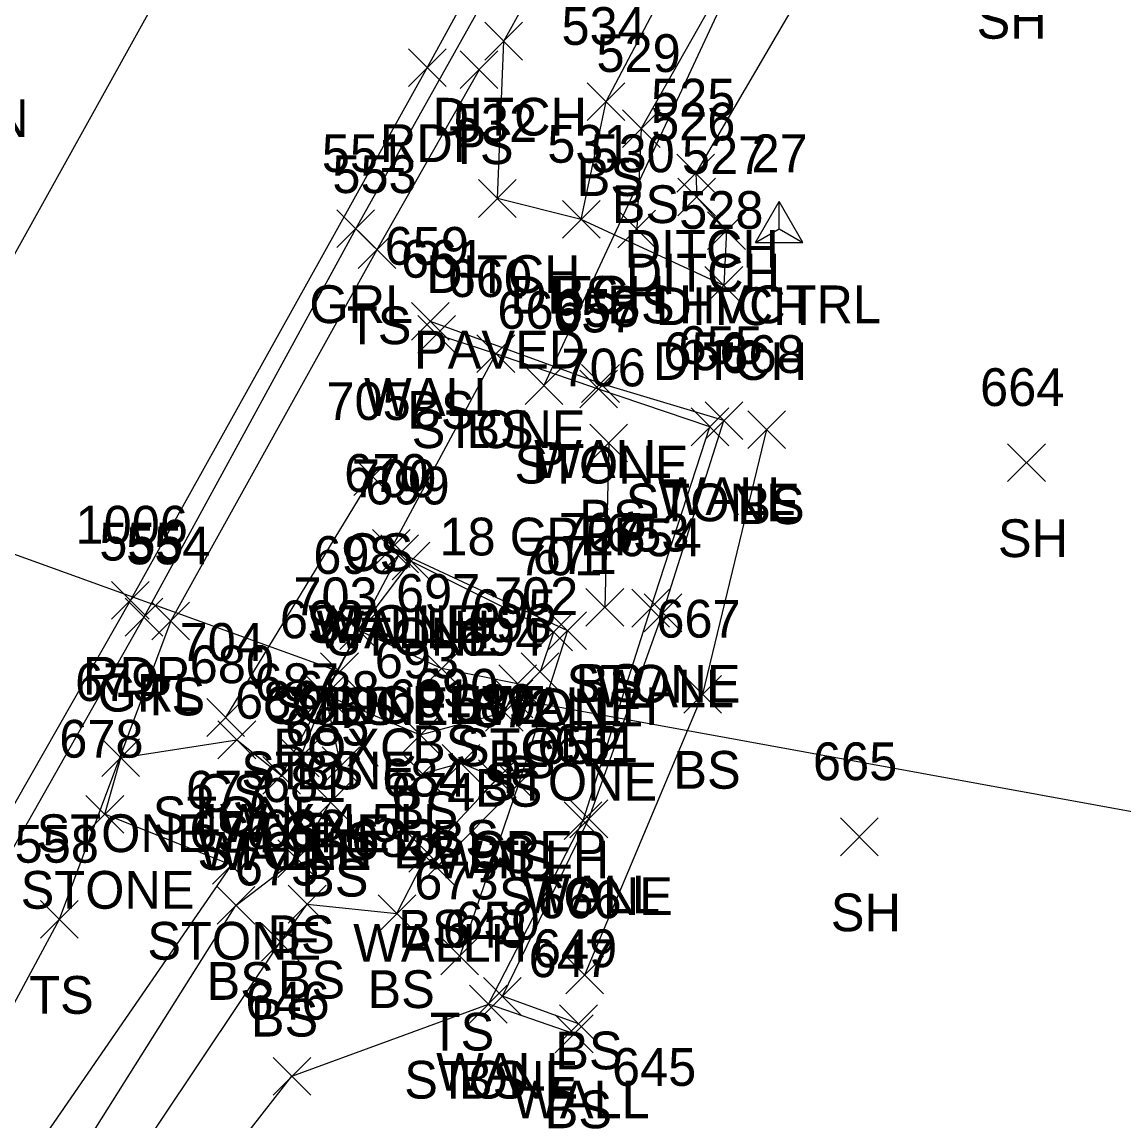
# Model space of a CAD drawing. Extents: x 1639430 to 1640195, y 612006 to 612917.
# Drawn here: x 1639849.6 to 1639907.9, y 612574.5 to 612632.7 of the extents above; entities that cross this region are included whole.
import ezdxf

# ---------------------------------------------------------------- set-up
doc = ezdxf.new("R2010")
doc.units = 0
for name, color, linetype in [('C_A', 7, 'Continuous'), ('C_C', 7, 'Continuous'), ('C_I', 7, 'Continuous'), ('CPSM', 7, 'Continuous'), ('D_A', 7, 'Continuous'), ('D_C', 7, 'Continuous'), ('D_I', 7, 'Continuous'), ('D_TIC', 7, 'Continuous'), ('DCP', 7, 'Continuous'), ('DD', 7, 'Continuous'), ('DDEFAULT', 7, 'Continuous'), ('DHW', 7, 'Continuous'), ('L_A', 7, 'Continuous'), ('L_I', 7, 'Continuous'), ('L_TIC', 7, 'Continuous'), ('LASF', 7, 'Continuous'), ('LELB', 7, 'Continuous'), ('LW', 7, 'Continuous'), ('P_A', 7, 'Continuous'), ('P_I', 7, 'Continuous'), ('P_TIC', 7, 'Continuous'), ('PET', 7, 'Continuous'), ('PRC', 7, 'Continuous'), ('R_A', 7, 'Continuous'), ('R_I', 7, 'Continuous'), ('R_TIC', 7, 'Continuous'), ('RGR', 7, 'Continuous')]:
    doc.layers.add(name, color=color, linetype=linetype)

msp = doc.modelspace()

# ---------------------------------------------------------------- linework, layer by layer
at = {"layer": 'CPSM'}
for p, q in [((1639888.428, 612621.012), (1639889.678, 612623.177)), ((1639890.928, 612621.012), (1639889.678, 612623.177)), ((1639889.678, 612621.733), (1639889.678, 612623.177)), ((1639888.428, 612621.012), (1639889.678, 612621.733)), ((1639889.678, 612621.733), (1639889.678, 612621.733)), ((1639889.678, 612621.733), (1639890.928, 612621.012)), ((1639888.428, 612621.012), (1639890.928, 612621.012))]:
    msp.add_line(p, q, dxfattribs=at)
at = {"layer": 'D_TIC'}
for points in [[(1639874.09, 612630.669), (1639876.09, 612632.669)], [(1639876.09, 612630.669), (1639874.09, 612632.669)], [(1639884.255, 612623.678), (1639886.255, 612625.678)], [(1639886.255, 612623.678), (1639884.255, 612625.678)], [(1639884.313, 612622.413), (1639886.313, 612624.413)], [(1639886.313, 612622.413), (1639884.313, 612624.413)], [(1639873.754, 612622.337), (1639875.754, 612624.337)], [(1639875.754, 612622.337), (1639873.754, 612624.337)], [(1639878.193, 612621.233), (1639880.193, 612623.233)], [(1639880.193, 612621.233), (1639878.193, 612623.233)], [(1639885.889, 612620.636), (1639887.889, 612622.636)], [(1639887.889, 612620.636), (1639885.889, 612622.636)], [(1639885.744, 612617.731), (1639887.744, 612619.731)], [(1639887.744, 612617.731), (1639885.744, 612619.731)], [(1639876.218, 612612.44), (1639878.218, 612614.44)], [(1639878.218, 612612.44), (1639876.218, 612614.44)], [(1639868.136, 612603.807), (1639870.136, 612605.807)], [(1639870.136, 612603.807), (1639868.136, 612605.807)], [(1639868.576, 612603.524), (1639870.576, 612605.524)], [(1639870.576, 612603.524), (1639868.576, 612605.524)], [(1639877.465, 612599.461), (1639879.465, 612601.461)], [(1639879.465, 612599.461), (1639877.465, 612601.461)], [(1639865.389, 612597.276), (1639867.389, 612599.276)], [(1639867.389, 612597.276), (1639865.389, 612599.276)], [(1639874.639, 612595.85), (1639876.639, 612597.85)], [(1639876.639, 612595.85), (1639874.639, 612597.85)], [(1639862.324, 612591.794), (1639864.324, 612593.794)], [(1639864.324, 612591.794), (1639862.324, 612593.794)], [(1639874.873, 612591.337), (1639876.873, 612593.337)], [(1639876.873, 612591.337), (1639874.873, 612593.337)], [(1639870.528, 612586.927), (1639872.528, 612588.927)], [(1639872.528, 612586.927), (1639870.528, 612588.927)]]:
    msp.add_lwpolyline(points, dxfattribs=at)
at = {"layer": 'DCP'}
for points in [[(1639918.116, 612701.079), (1639877.218, 612613.44)], [(1639875.639, 612596.85), (1640140.731, 612548.532)]]:
    msp.add_lwpolyline(points, dxfattribs=at)
at = {"layer": 'DD'}
msp.add_lwpolyline([(1639902.176, 612653.77), (1639894.751, 612640.906), (1639885.255, 612624.678), (1639885.313, 612623.413), (1639886.889, 612621.636), (1639886.744, 612618.731), (1639879.193, 612622.233), (1639874.754, 612623.337), (1639875.09, 612631.669), (1639888.012, 612654.984), (1639893.23, 612659.527), (1639898.686, 612662.04)], dxfattribs=at)
at = {"layer": 'DDEFAULT'}
msp.add_lwpolyline([(1639866.389, 612598.276), (1639824.748, 612613.308)], dxfattribs=at)
at = {"layer": 'DHW'}
for points in [[(1639869.136, 612604.807), (1639878.465, 612600.461), (1639875.873, 612592.337), (1639871.528, 612587.927)], [(1639863.324, 612592.794), (1639869.576, 612604.524)]]:
    msp.add_lwpolyline(points, dxfattribs=at)
at = {"layer": 'L_TIC'}
for points in [[(1639872.784, 612629.158), (1639874.784, 612631.158)], [(1639874.784, 612629.158), (1639872.784, 612631.158)], [(1639879.51, 612627.471), (1639881.51, 612629.471)], [(1639881.51, 612627.471), (1639879.51, 612629.471)], [(1639881.371, 612626.037), (1639883.371, 612628.037)], [(1639883.371, 612626.037), (1639881.371, 612628.037)], [(1639878.193, 612621.233), (1639880.193, 612623.233)], [(1639880.193, 612621.233), (1639878.193, 612623.233)], [(1639881.132, 612620.728), (1639883.132, 612622.728)], [(1639883.132, 612620.728), (1639881.132, 612622.728)], [(1639881.132, 612620.728), (1639883.132, 612622.728)], [(1639883.132, 612620.728), (1639881.132, 612622.728)], [(1639867.375, 612619.626), (1639869.375, 612621.626)], [(1639869.375, 612619.626), (1639867.375, 612621.626)], [(1639870.204, 612615.83), (1639872.204, 612617.83)], [(1639872.204, 612615.83), (1639870.204, 612617.83)], [(1639870.537, 612615.145), (1639872.537, 612617.145)], [(1639872.537, 612615.145), (1639870.537, 612617.145)], [(1639873.67, 612614.123), (1639875.67, 612616.123)], [(1639875.67, 612614.123), (1639873.67, 612616.123)], [(1639873.67, 612614.123), (1639875.67, 612616.123)], [(1639875.67, 612614.123), (1639873.67, 612616.123)], [(1639879.213, 612612.544), (1639881.213, 612614.544)], [(1639881.213, 612612.544), (1639879.213, 612614.544)], [(1639879.114, 612612.248), (1639881.114, 612614.248)], [(1639881.114, 612612.248), (1639879.114, 612614.248)], [(1639885.009, 612610.247), (1639887.009, 612612.247)], [(1639887.009, 612610.247), (1639885.009, 612612.247)], [(1639885.755, 612610.578), (1639887.755, 612612.578)], [(1639887.755, 612610.578), (1639885.755, 612612.578)], [(1639888.021, 612610.1), (1639890.021, 612612.1)], [(1639890.021, 612610.1), (1639888.021, 612612.1)], [(1639879.647, 612609.391), (1639881.647, 612611.391)], [(1639881.647, 612609.391), (1639879.647, 612611.391)], [(1639901.775, 612608.353), (1639903.775, 612610.353)], [(1639903.775, 612608.353), (1639901.775, 612610.353)], [(1639867.142, 612607.612), (1639869.142, 612609.612)], [(1639869.142, 612607.612), (1639867.142, 612609.612)], [(1639868.136, 612603.807), (1639870.136, 612605.807)], [(1639870.136, 612603.807), (1639868.136, 612605.807)], [(1639869.18, 612603.142), (1639871.18, 612605.142)], [(1639871.18, 612603.142), (1639869.18, 612605.142)], [(1639879.445, 612600.687), (1639881.445, 612602.687)], [(1639881.445, 612600.687), (1639879.445, 612602.687)], [(1639881.873, 612600.647), (1639883.873, 612602.647)], [(1639883.873, 612600.647), (1639881.873, 612602.647)], [(1639882.519, 612600.4), (1639884.519, 612602.4)], [(1639884.519, 612600.4), (1639882.519, 612602.4)], [(1639856.45, 612599.97), (1639858.45, 612601.97)], [(1639858.45, 612599.97), (1639856.45, 612601.97)], [(1639866.414, 612599.464), (1639868.414, 612601.464)], [(1639868.414, 612599.464), (1639866.414, 612601.464)], [(1639866.414, 612599.464), (1639868.414, 612601.464)], [(1639868.414, 612599.464), (1639866.414, 612601.464)], [(1639876.726, 612599.386), (1639878.726, 612601.386)], [(1639878.726, 612599.386), (1639876.726, 612601.386)], [(1639870.793, 612597.451), (1639872.793, 612599.451)], [(1639872.793, 612597.451), (1639870.793, 612599.451)], [(1639876.015, 612597.283), (1639878.015, 612599.283)], [(1639878.015, 612597.283), (1639876.015, 612599.283)], [(1639874.823, 612596.644), (1639876.823, 612598.644)], [(1639876.823, 612596.644), (1639874.823, 612598.644)], [(1639864.644, 612596.055), (1639866.644, 612598.055)], [(1639866.644, 612596.055), (1639864.644, 612598.055)], [(1639864.644, 612596.055), (1639866.644, 612598.055)], [(1639866.644, 612596.055), (1639864.644, 612598.055)], [(1639884.63, 612596.089), (1639886.63, 612598.089)], [(1639886.63, 612596.089), (1639884.63, 612598.089)], [(1639874.126, 612595.136), (1639876.126, 612597.136)], [(1639876.126, 612595.136), (1639874.126, 612597.136)], [(1639859.364, 612594.86), (1639861.364, 612596.86)], [(1639861.364, 612594.86), (1639859.364, 612596.86)], [(1639869.67, 612593.934), (1639871.67, 612595.934)], [(1639871.67, 612593.934), (1639869.67, 612595.934)], [(1639859.954, 612593.676), (1639861.954, 612595.676)], [(1639861.954, 612593.676), (1639859.954, 612595.676)], [(1639853.806, 612592.733), (1639855.806, 612594.733)], [(1639855.806, 612592.733), (1639853.806, 612594.733)], [(1639863.307, 612592.727), (1639865.307, 612594.727)], [(1639865.307, 612592.727), (1639863.307, 612594.727)], [(1639865.468, 612592.314), (1639867.468, 612594.314)], [(1639867.468, 612592.314), (1639865.468, 612594.314)], [(1639871.829, 612592.434), (1639873.829, 612594.434)], [(1639873.829, 612592.434), (1639871.829, 612594.434)], [(1639862.324, 612591.794), (1639864.324, 612593.794)], [(1639864.324, 612591.794), (1639862.324, 612593.794)], [(1639869.798, 612591.872), (1639871.798, 612593.872)], [(1639871.798, 612591.872), (1639869.798, 612593.872)], [(1639873.751, 612591.625), (1639875.751, 612593.625)], [(1639875.751, 612591.625), (1639873.751, 612593.625)], [(1639874.873, 612591.337), (1639876.873, 612593.337)], [(1639876.873, 612591.337), (1639874.873, 612593.337)], [(1639864.918, 612590.379), (1639866.918, 612592.379)], [(1639866.918, 612590.379), (1639864.918, 612592.379)], [(1639852.96, 612589.734), (1639854.96, 612591.734)], [(1639854.96, 612589.734), (1639852.96, 612591.734)], [(1639878.29, 612589.4), (1639880.29, 612591.4)], [(1639880.29, 612589.4), (1639878.29, 612591.4)], [(1639878.594, 612589.493), (1639880.594, 612591.493)], [(1639880.594, 612589.493), (1639878.594, 612591.493)], [(1639892.924, 612588.541), (1639894.924, 612590.541)], [(1639894.924, 612588.541), (1639892.924, 612590.541)], [(1639870.064, 612587.676), (1639872.064, 612589.676)], [(1639872.064, 612587.676), (1639870.064, 612589.676)], [(1639859.668, 612587.037), (1639861.668, 612589.037)], [(1639861.668, 612587.037), (1639859.668, 612589.037)], [(1639863.13, 612587.383), (1639865.13, 612589.383)], [(1639865.13, 612587.383), (1639863.13, 612589.383)], [(1639859.907, 612584.911), (1639861.907, 612586.911)], [(1639861.907, 612584.911), (1639859.907, 612586.911)], [(1639863.681, 612584.978), (1639865.681, 612586.978)], [(1639865.681, 612584.978), (1639863.681, 612586.978)], [(1639868.432, 612584.476), (1639870.432, 612586.476)], [(1639870.432, 612584.476), (1639868.432, 612586.476)], [(1639850.548, 612584.172), (1639852.548, 612586.172)], [(1639852.548, 612584.172), (1639850.548, 612586.172)], [(1639862.256, 612582.967), (1639864.256, 612584.967)], [(1639864.256, 612582.967), (1639862.256, 612584.967)], [(1639871.76, 612582.227), (1639873.76, 612584.227)], [(1639873.76, 612582.227), (1639871.76, 612584.227)], [(1639878.379, 612581.231), (1639880.379, 612583.231)], [(1639880.379, 612581.231), (1639878.379, 612583.231)], [(1639874.02, 612580.102), (1639876.02, 612582.102)], [(1639876.02, 612580.102), (1639874.02, 612582.102)], [(1639873.276, 612579.681), (1639875.276, 612581.681)], [(1639875.276, 612579.681), (1639873.276, 612581.681)], [(1639873.276, 612579.681), (1639875.276, 612581.681)], [(1639875.276, 612579.681), (1639873.276, 612581.681)], [(1639878.051, 612578.64), (1639880.051, 612580.64)], [(1639880.051, 612578.64), (1639878.051, 612580.64)], [(1639877.818, 612578.112), (1639879.818, 612580.112)], [(1639879.818, 612578.112), (1639877.818, 612580.112)], [(1639862.872, 612575.867), (1639864.872, 612577.867)], [(1639864.872, 612575.867), (1639862.872, 612577.867)]]:
    msp.add_lwpolyline(points, dxfattribs=at)
at = {"layer": 'LASF'}
for points in [[(1639840.772, 612546.338), (1639850.85, 612560.212), (1639863.872, 612576.867), (1639874.276, 612580.681), (1639879.29, 612590.4), (1639882.873, 612601.647), (1639886.009, 612611.247), (1639880.114, 612613.248), (1639874.67, 612615.123), (1639869.136, 612604.807)], [(1639840.772, 612546.338), (1639838.927, 612546.332), (1639837.461, 612546.877), (1639836.3, 612547.416), (1639834.93, 612548.334), (1639843.668, 612563.409), (1639860.668, 612588.037), (1639853.96, 612590.734), (1639854.806, 612593.733), (1639860.954, 612594.676), (1639863.324, 612592.794), (1639864.307, 612593.727), (1639865.644, 612597.055), (1639867.414, 612600.464), (1639870.18, 612604.142), (1639877.726, 612600.386), (1639877.015, 612598.283)]]:
    msp.add_lwpolyline(points, dxfattribs=at)
at = {"layer": 'LELB'}
for points in [[(1639879.193, 612622.233), (1639880.51, 612628.471), (1639893.458, 612653.006), (1639899.016, 612658.821)], [(1639898.799, 612654.769), (1639891.617, 612643.364), (1639882.371, 612627.037), (1639882.132, 612621.728)], [(1639873.784, 612630.158), (1639868.375, 612620.626), (1639857.45, 612600.97), (1639851.548, 612585.172), (1639842.168, 612567.758), (1639826.769, 612543.6), (1639823.114, 612538.523), (1639804.665, 612509.817), (1639793.927, 612486.538)], [(1639874.67, 612615.123), (1639871.537, 612616.145)], [(1639879.379, 612582.231), (1639885.63, 612597.089), (1639889.021, 612611.1)], [(1639880.647, 612610.391), (1639880.445, 612601.687)], [(1639860.364, 612595.86), (1639868.142, 612608.612)], [(1639836.3, 612547.416), (1639846.143, 612562.496), (1639860.907, 612585.911), (1639864.13, 612588.383), (1639865.918, 612591.379), (1639866.468, 612593.314), (1639865.644, 612597.055), (1639870.67, 612594.934), (1639875.126, 612596.136), (1639875.823, 612597.644), (1639871.793, 612598.451), (1639867.414, 612600.464)], [(1639836.3, 612547.416), (1639848.433, 612561.824), (1639863.256, 612583.967), (1639864.681, 612585.978), (1639869.432, 612585.476), (1639871.064, 612588.676), (1639874.751, 612592.625), (1639872.829, 612593.434), (1639870.798, 612592.872)], [(1639875.873, 612592.337), (1639872.76, 612583.227)], [(1639878.818, 612579.112), (1639874.276, 612580.681)]]:
    msp.add_lwpolyline(points, dxfattribs=at)
at = {"layer": 'LW'}
msp.add_lwpolyline([(1639879.051, 612579.64), (1639875.02, 612581.102), (1639879.594, 612590.493), (1639883.519, 612601.4), (1639886.755, 612611.578), (1639880.213, 612613.544), (1639871.204, 612616.83)], dxfattribs=at)
at = {"layer": 'P_TIC'}
for points in [[(1639870.039, 612629.269), (1639872.039, 612631.269)], [(1639872.039, 612629.269), (1639870.039, 612631.269)], [(1639854.317, 612601.067), (1639856.317, 612603.067)], [(1639856.317, 612601.067), (1639854.317, 612603.067)]]:
    msp.add_lwpolyline(points, dxfattribs=at)
at = {"layer": 'PET'}
msp.add_lwpolyline([(1639889.959, 612664.779), (1639871.039, 612630.269), (1639855.317, 612602.067), (1639833.916, 612564.51), (1639815.495, 612533.184), (1639791.067, 612492.272)], dxfattribs=at)
at = {"layer": 'PRC'}
msp.add_lwpolyline([(1639858.802, 612637.722), (1639842.594, 612608.574), (1639822.132, 612572.441), (1639804.172, 612540.707), (1639777.378, 612495.693)], dxfattribs=at)
at = {"layer": 'R_TIC'}
for points in [[(1639866.25, 612620.742), (1639868.25, 612622.742)], [(1639868.25, 612620.742), (1639866.25, 612622.742)], [(1639855.032, 612600.171), (1639857.032, 612602.171)], [(1639857.032, 612600.171), (1639855.032, 612602.171)]]:
    msp.add_lwpolyline(points, dxfattribs=at)
at = {"layer": 'RGR'}
msp.add_lwpolyline([(1639895.623, 612663.083), (1639891.964, 612661.302), (1639887.868, 612657.734), (1639885.714, 612654.678), (1639867.25, 612621.742), (1639856.032, 612601.171), (1639838.745, 612570.685), (1639824.789, 612544.939), (1639823.114, 612538.523), (1639823.733, 612532.824)], dxfattribs=at)

# ---------------------------------------------------------------- texts
at = {"layer": 'C_A'}
msp.add_text('HVCTRL', height=2, dxfattribs=at).set_placement((1639884.371, 612616.733))
at = {"layer": 'C_C'}
msp.add_text('TOP OF BOLT AFTER ARROW ON', height=2, dxfattribs=at).set_placement((1639806.981, 612626.592))
at = {"layer": 'C_I'}
msp.add_text('27', height=2, dxfattribs=at).set_placement((1639888.213, 612624.733))
at = {"layer": 'D_A'}
for s, p in [('DITCH', (1639871.326, 612626.669)), ('DITCH', (1639881.491, 612619.678)), ('DITCH', (1639870.99, 612618.337)), ('DITCH', (1639881.549, 612618.413)), ('DITCH', (1639875.429, 612617.233)), ('DITCH', (1639883.125, 612616.636)), ('DITCH', (1639882.98, 612613.731)), ('P', (1639876.596, 612608.44)), ('WALLH', (1639864.727, 612599.807)), ('WALLH', (1639865.166, 612599.524)), ('WALLH', (1639874.055, 612595.461)), ('BOXC', (1639862.885, 612593.276)), ('P', (1639875.017, 612591.85)), ('WALLH', (1639858.914, 612587.794)), ('WALLH', (1639871.464, 612587.337)), ('WALLH', (1639867.118, 612582.927))]:
    msp.add_text(s, height=2, dxfattribs=at).set_placement(p)
at = {"layer": 'D_C'}
for s, p in [('PAVED', (1639870.337, 612614.337)), ('18 CPEP', (1639871.682, 612604.44)), ('CONCRETE', (1639862.332, 612595.524)), ('STONE', (1639874.008, 612591.461)), ('4W X 4.5H', (1639858.578, 612589.276)), ('42 CPEP', (1639869.537, 612587.85))]:
    msp.add_text(s, height=2, dxfattribs=at).set_placement(p)
at = {"layer": 'D_I'}
for s, p in [('525', (1639882.893, 612627.678)), ('532', (1639872.392, 612626.337)), ('526', (1639882.895, 612626.413)), ('531', (1639877.397, 612625.233)), ('527', (1639884.527, 612624.636)), ('528', (1639884.382, 612621.731)), ('669', (1639874.753, 612616.44)), ('670', (1639866.64, 612607.807)), ('700', (1639867.048, 612607.524)), ('671', (1639876.622, 612603.461)), ('703', (1639863.948, 612601.276)), ('696', (1639873.175, 612599.85)), ('686', (1639860.859, 612595.794)), ('672', (1639873.464, 612595.337)), ('674', (1639869.118, 612590.927))]:
    msp.add_text(s, height=2, dxfattribs=at).set_placement(p)
at = {"layer": 'L_A'}
for s, p in [('SH', (1639900.132, 612631.799)), ('TS', (1639872.194, 612625.158)), ('BS', (1639878.951, 612623.471)), ('BS', (1639880.812, 612622.037)), ('BS', (1639877.634, 612617.233)), ('BS', (1639880.573, 612616.728)), ('BS', (1639880.573, 612616.728)), ('TS', (1639866.784, 612615.626)), ('WALL', (1639867.693, 612611.83)), ('BS', (1639869.978, 612611.145)), ('STONE', (1639870.213, 612610.123)), ('BS', (1639873.111, 612610.123)), ('WALL', (1639876.701, 612608.544)), ('STONE', (1639875.657, 612608.248)), ('STONE', (1639881.552, 612606.247)), ('WALL', (1639883.244, 612606.578)), ('BS', (1639887.462, 612606.1)), ('BS', (1639879.088, 612605.391)), ('SH', (1639901.263, 612604.353)), ('CS', (1639866.583, 612603.612)), ('STONE', (1639864.68, 612599.807)), ('STONE', (1639865.723, 612599.142)), ('STONE', (1639878.416, 612596.647)), ('BS', (1639878.886, 612596.687)), ('WALL', (1639880.007, 612596.4)), ('TS', (1639855.859, 612595.97)), ('STONE', (1639862.957, 612595.464)), ('BS', (1639865.855, 612595.464)), ('STONE', (1639873.269, 612595.386)), ('BS', (1639870.234, 612593.451)), ('STONE', (1639872.559, 612593.283)), ('BS', (1639874.264, 612592.644)), ('STONE', (1639861.187, 612592.055)), ('BS', (1639864.085, 612592.055)), ('BS', (1639884.071, 612592.089)), ('CS', (1639858.805, 612590.86)), ('BS', (1639873.567, 612591.136)), ('BS', (1639869.111, 612589.934)), ('STONE', (1639856.497, 612589.676)), ('STONE', (1639850.349, 612588.733)), ('STONE', (1639859.85, 612588.727)), ('BS', (1639864.909, 612588.314)), ('BS', (1639871.27, 612588.434)), ('STONE', (1639858.867, 612587.794)), ('BS', (1639869.239, 612587.872)), ('BS', (1639873.192, 612587.625)), ('TS', (1639874.283, 612587.337)), ('BS', (1639864.359, 612586.379)), ('STONE', (1639849.503, 612585.734)), ('STONE', (1639874.833, 612585.4)), ('WALL', (1639876.082, 612585.493)), ('SH', (1639892.412, 612584.541)), ('BS', (1639862.571, 612583.383)), ('BS', (1639869.505, 612583.676)), ('STONE', (1639856.212, 612583.037)), ('BS', (1639863.122, 612580.978)), ('BS', (1639859.348, 612580.911)), ('BS', (1639867.873, 612580.476)), ('TS', (1639849.957, 612580.172)), ('BS', (1639861.697, 612578.967)), ('TS', (1639871.169, 612578.227)), ('BS', (1639877.82, 612577.231)), ('WALL', (1639871.508, 612576.102)), ('STONE', (1639869.819, 612575.681)), ('BS', (1639872.717, 612575.681)), ('WALL', (1639875.539, 612574.64)), ('BS', (1639877.258, 612574.112))]:
    msp.add_text(s, height=2, dxfattribs=at).set_placement(p)
at = {"layer": 'L_I'}
for s, p in [('534', (1639878.148, 612631.471)), ('529', (1639880.001, 612630.037)), ('531', (1639877.397, 612625.233)), ('530', (1639879.683, 612624.728)), ('530', (1639879.683, 612624.728)), ('553', (1639866.012, 612623.626)), ('659', (1639868.787, 612619.83)), ('661', (1639869.647, 612619.145)), ('660', (1639872.127, 612618.123)), ('660', (1639872.127, 612618.123)), ('658', (1639877.804, 612616.544)), ('657', (1639877.704, 612616.248)), ('656', (1639883.544, 612614.247)), ('655', (1639884.346, 612614.578)), ('668', (1639886.564, 612614.1)), ('706', (1639878.151, 612613.391)), ('664', (1639900.318, 612612.353)), ('705', (1639865.701, 612611.612)), ('670', (1639866.64, 612607.807)), ('699', (1639867.763, 612607.142)), ('707', (1639878.004, 612604.687)), ('653', (1639880.463, 612604.647)), ('654', (1639881.109, 612604.4)), ('554', (1639855.087, 612603.97)), ('698', (1639865.005, 612603.464)), ('698', (1639865.005, 612603.464)), ('701', (1639875.852, 612603.386)), ('697', (1639869.384, 612601.451)), ('702', (1639874.574, 612601.283)), ('695', (1639873.414, 612600.644)), ('692', (1639863.234, 612600.055)), ('692', (1639863.234, 612600.055)), ('667', (1639883.173, 612600.089)), ('694', (1639872.717, 612599.136)), ('704', (1639857.923, 612598.86)), ('693', (1639868.26, 612597.934)), ('680', (1639858.458, 612597.676)), ('679', (1639852.389, 612596.733)), ('687', (1639861.897, 612596.727)), ('688', (1639864.058, 612596.314)), ('690', (1639870.333, 612596.434)), ('686', (1639860.859, 612595.794)), ('691', (1639868.956, 612595.872)), ('689', (1639872.334, 612595.625)), ('672', (1639873.464, 612595.337)), ('685', (1639863.509, 612594.379)), ('678', (1639851.55, 612593.734)), ('652', (1639876.881, 612593.4)), ('651', (1639877.752, 612593.493)), ('665', (1639891.467, 612592.541)), ('684', (1639868.654, 612591.676)), ('677', (1639858.259, 612591.037)), ('681', (1639862.288, 612591.383)), ('676', (1639858.442, 612588.911)), ('682', (1639862.271, 612588.978)), ('558', (1639849.186, 612588.172)), ('683', (1639867.022, 612588.476)), ('675', (1639860.847, 612586.967)), ('673', (1639870.351, 612586.227)), ('666', (1639876.867, 612585.231)), ('650', (1639872.524, 612584.102)), ('648', (1639871.867, 612583.681)), ('648', (1639871.867, 612583.681)), ('647', (1639876.408, 612582.112)), ('649', (1639876.633, 612582.64)), ('646', (1639861.407, 612579.867)), ('645', (1639880.822, 612576.357))]:
    msp.add_text(s, height=2, dxfattribs=at).set_placement(p)
at = {"layer": 'P_A'}
for p in [(1639868.528, 612625.269), (1639852.805, 612597.067)]:
    msp.add_text('RDP', height=2, dxfattribs=at).set_placement(p)
at = {"layer": 'P_I'}
msp.add_text('1006', height=2, dxfattribs=at).set_placement((1639852.411, 612605.067))
at = {"layer": 'R_A'}
for p in [(1639864.793, 612616.742), (1639853.575, 612596.171)]:
    msp.add_text('GRL', height=2, dxfattribs=at).set_placement(p)
at = {"layer": 'R_I'}
for s, p in [('551', (1639865.455, 612624.742)), ('555', (1639853.67, 612604.171))]:
    msp.add_text(s, height=2, dxfattribs=at).set_placement(p)

doc.saveas('drawing.dxf')
